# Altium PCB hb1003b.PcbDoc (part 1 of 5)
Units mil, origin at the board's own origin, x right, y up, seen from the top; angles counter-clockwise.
Board outline 2757 x 3548 mil, 2 copper layers (Top Layer, Bottom Layer); 120 components, 120 nets, 466 pads, 329 vias.
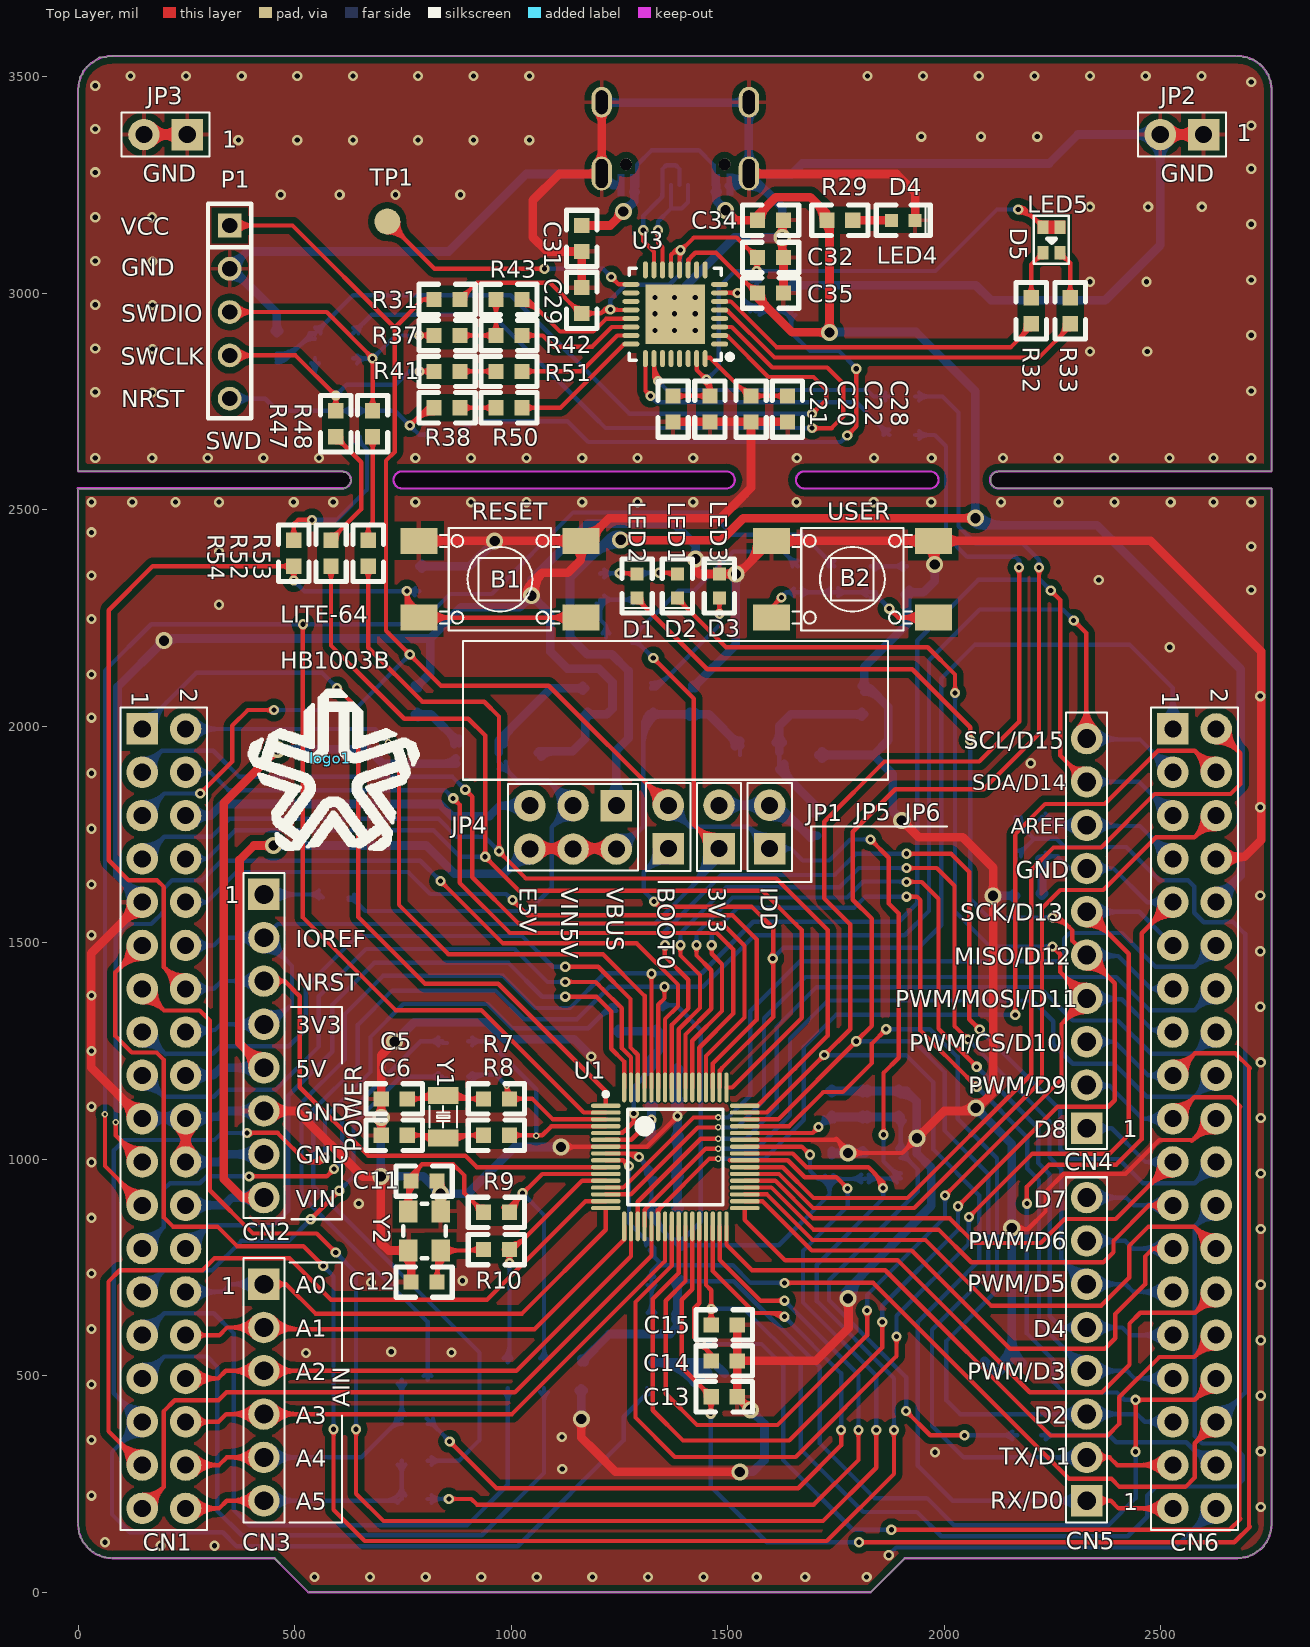
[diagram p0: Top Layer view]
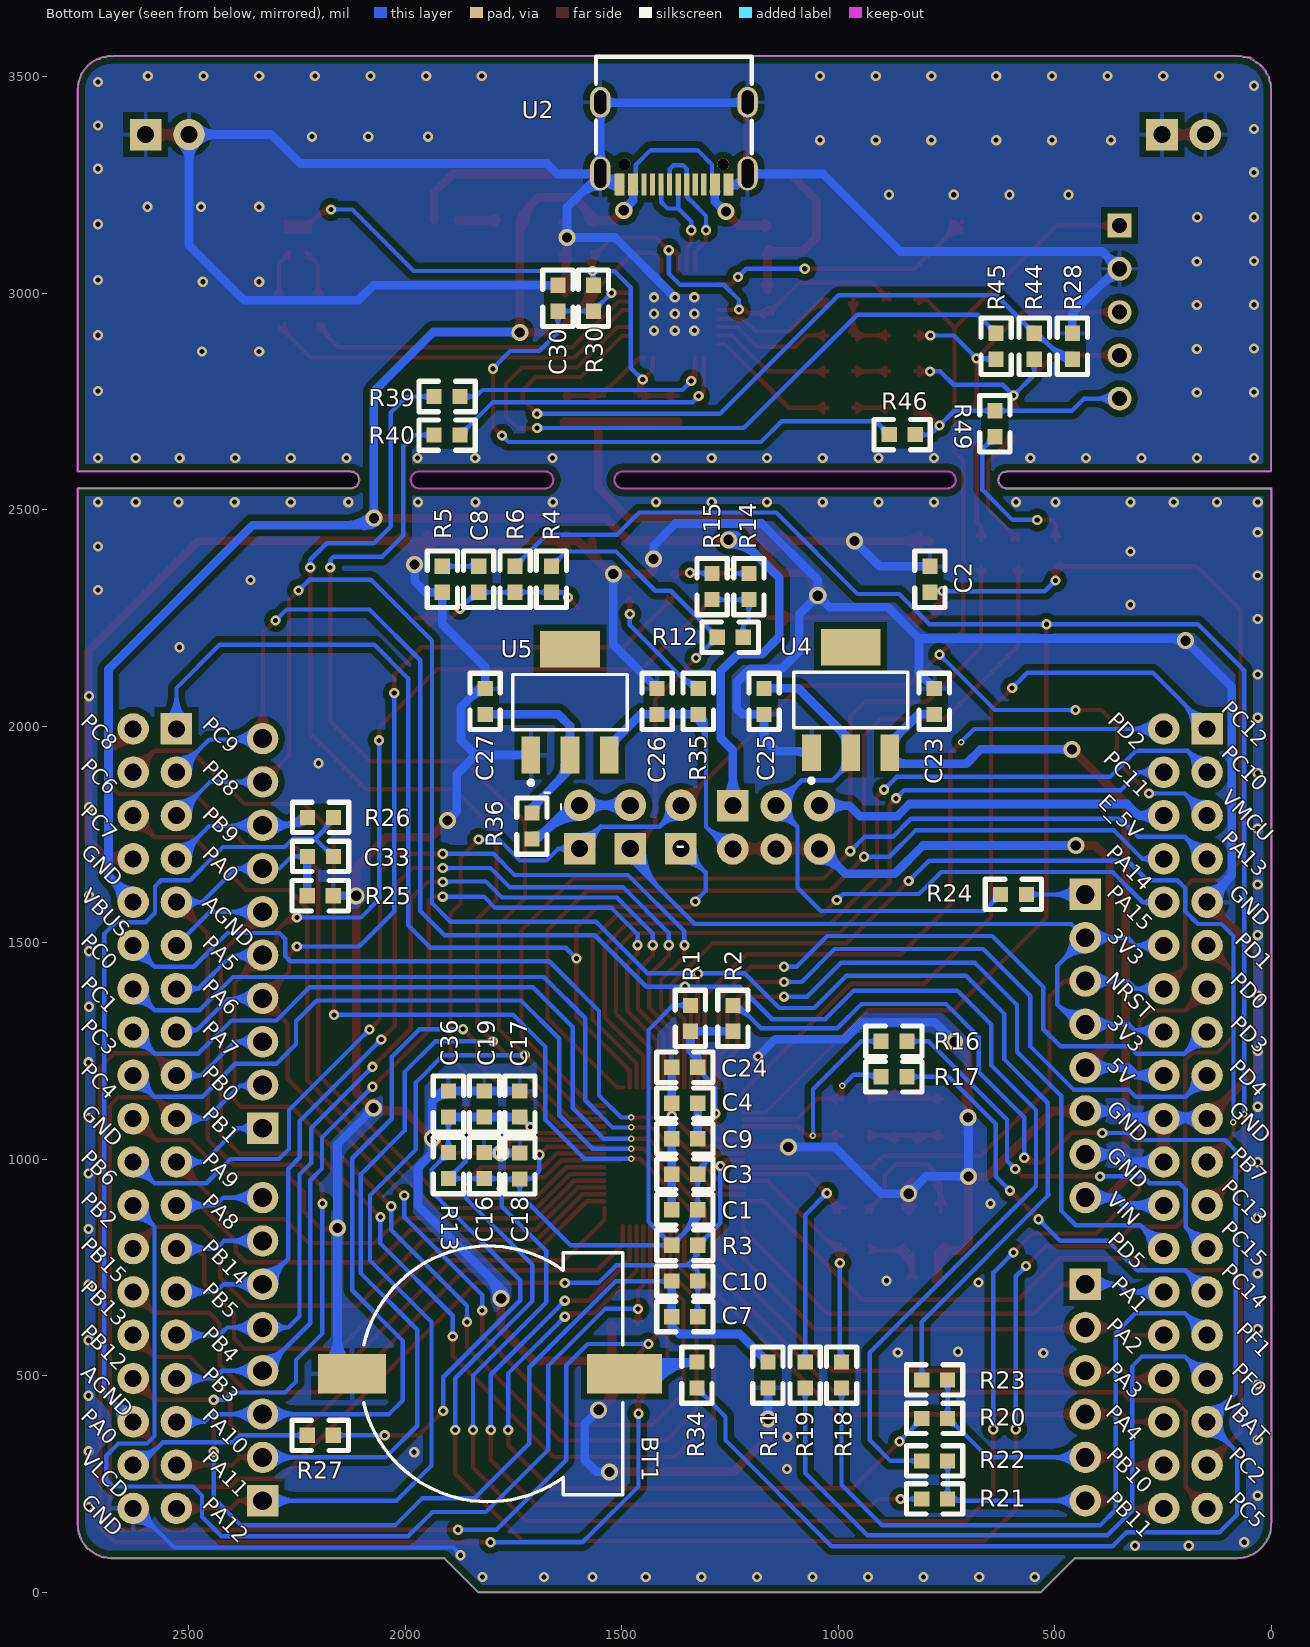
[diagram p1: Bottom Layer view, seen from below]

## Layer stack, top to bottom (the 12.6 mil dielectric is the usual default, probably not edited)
Top Layer: signal copper 1.4
Dielectric: dielectric 12.6, FR-4, Dk 4.8
Bottom Layer: signal copper 1.4

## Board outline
79,3548 2667,3548 2674,3548 2675,3547 2681,3547 2687,3547 2689,3545 2695,3545 2700,3545 2701,3544 2705,3540 2708,3540 2713,3540 2714,3539 2717,3536 2720,3536 2724,3532 2727,3529 2728,3529 2729,3529 2732,3526 2734,3524 2734,3523 2737,3520 2740,3517 2740,3515 2743,3512 2745,3510 2745,3509 2747,3507 2749,3505 2749,3500 2749,3499 2750,3498 2751,3497 2751,3496 2751,3494 2753,3492 2754,3491 2754,3489 2754,3486 2755,3485 2755,3480 2755,3476 2756,3475 2756,3470 2756,2588 2129,2588 2125,2588 2124,2587 2123,2586 2119,2586 2117,2586 2116,2585 2114,2583 2113,2583 2112,2582 2111,2581 2111,2580 2110,2580 2109,2579 2109,2577 2108,2576 2108,2573 2107,2572 2107,2566 2107,2562 2108,2561 2110,2559 2110,2555 2111,2555 2112,2554 2113,2553 2115,2553 2116,2553 2118,2551 2119,2550 2120,2550 2122,2550 2123,2549 2127,2549 2756,2549 2756,156 2756,153 2755,152 2755,149 2755,146 2755,143 2755,140 2754,139 2753,138 2753,137 2753,135 2752,134 2751,133 2751,131 2751,127 2750,126 2748,124 2748,122 2748,121 2747,120 2746,119 2746,118 2746,116 2745,115 2742,112 2742,111 2741,111 2740,110 2739,109 2739,108 2739,105 2738,104 2737,103 2737,102 2737,104 2736,103 2736,102 2735,101 2733,99 2732,99 2729,99 2727,97 2724,94 2723,94 2721,94 2718,91 2716,89 2716,88 2714,88 2712,86 2711,85 2708,85 2706,85 2704,83 2702,81 2698,81 2695,81 2694,80 2688,80 2687,79 2686,78 2678,78 1909,78 1858,27 1831,0 1734,0 532,0 481,51 454,78 426,78 78,78 77,79 73,79 70,79 68,79 65,79 64,80 63,81 62,81 59,81 58,82 57,82 53,82 50,85 49,86 46,86 44,86 43,87 42,88 41,88 40,88 38,90 35,93 33,93 32,93 30,95 28,97 28,99 26,99 25,100 21,104 21,105 19,107 17,109 17,110 14,113 10,117 10,119 10,121 8,123 5,126 5,127 5,130 4,131 2,133 2,134 2,137 1,138 1,142 1,149 0,150 0,154 0,159 -1,160 -1,2548 613,2548 614,2549 615,2550 617,2550 618,2550 619,2551 621,2553 622,2554 624,2556 626,2558 628,2560 628,2562 629,2563 631,2565 631,2566 631,2569 630,2570 628,2572 628,2576 628,2578 626,2580 624,2582 624,2583 623,2583 621,2585 620,2586 617,2586 613,2586 612,2587 611,2588 608,2588 605,2588 0,2588 0,3474 1,3475 1,3481 1,3486 3,3488 4,3489 4,3494 4,3499 7,3502 11,3506 11,3510 11,3513 15,3517 19,3521 19,3522 20,3522 23,3525 30,3532 35,3532 41,3538 48,3545 59,3545 66,3545 67,3546 68,3547 79,3547 80,3547
cut-out: 1678.42,2547.63 1967,2547.63 ccw(c1967,2567.31) 1967,2587 1678.42,2587 ccw(c1678.42,2567.32)
cut-out: 747.97,2549 1496,2549 ccw(c1496,2568.68) 1496,2588.37 747.97,2588.37 ccw(c747.97,2568.68)

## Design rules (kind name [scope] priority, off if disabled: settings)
Clearance [(IsPad and InComponent('U1'))] p1: gap=4
Clearance Clearance_poly [(InPolygon)] p2: gap=15
Clearance Clearance_CN [(IsPad and InComponent('CN1','CN4'))] p3: gap=5
Clearance Clearance_Pad [All] p4: gap=5
ComponentClearance [All] p1: gap=0 collisioncheckmode=3 verticalgap=0 showdistances=FALSE
HoleSize [All] p1: absolutevalues=TRUE maxlimit=130 minlimit=1 maxpercent=80.000 minpercent=20.000
MinimumSolderMaskSliver [All] p1: minsoldermaskwidth=0
PolygonConnect PolygonConnect_Pads [IsPad] p1: connectstyle=Relief reliefconductorwidth=10 reliefentries=4 polygonreliefangle="90 Angle"
PolygonConnect [All] p2: connectstyle=Direct reliefconductorwidth=10 reliefentries=4 polygonreliefangle="90 Angle"
RoutingVias [All] p1: holewidth=12 width=20 viastyle="Through Hole" minholewidth=10 minwidth=18 maxholewidth=300 maxwidth=500
SilkToSilkClearance [All] p1: silktosilkclearance=0
SilkscreenOverComponentPads [IsPad] p1: minsilkscreentomaskgap=0
SolderMaskExpansion [All] p1: expansion=4
TestPointUsage [All] p1: valid=0 allowmultiple=FALSE
Testpoint [All] p1: side=3 testpointundercomponent=TRUE minsize=40 maxsize=100 preferedsize=60 minholesize=0 maxholesize=40 preferedholesize=32 testpointgrid=1 style=297 order=0123456789
Width [All] p1: maxlimit=20 minlimit=8 preferedwidth=10
19 further rules are at their usual default settings.

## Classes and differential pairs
net class PD[0..5]: PD0 PD1 PD2 PD3 PD4 PD5
net class PC[0..15]: PC0 PC1 PC2 PC3 PC4 PC5 PC6 PC7 PC8 PC9 PC10 PC11 PC12 PC13 PC14 PC15
component class hed_link: C20 C21 C22 C28 C29 C30 C31 C32 C34 C35 D4 D5 JP7 JP8 JP9 JP10 JP11 LD1 P1 R28 R29 R30 R31 R32 R33 R37 R38 R39 R40 R41 R42 R43 R44 R45 R46 R47 R48 R49 R50 R51 TP1 U2 U3
component class arduino_extension_interfaces: C19 CN1 CN2 CN3 CN4 CN5 CN6 R16 R17 R18 R19 R20 R21 R22 R23 R24 R25 R26 R27
component class mcu: B1 B2 C1 C2 C3 C4 C5 C6 C7 C8 C9 C10 C11 C12 C13 C14 C15 C16 C17 C18 C24 C33 C36 D1 D2 JP1 logo1 R1 R2 R3 R4 R5 R6 R7 R8 R9 R10 R11 R12 R13 R14 R15 R52 R53 R54 U1 Y1 Y2
component class power: BT1 C23 C25 C26 C27 D3 JP2 JP3 JP4 JP5 JP6 R34 R35 R36 U4 U5
net class PA[0..15]: PA0 PA1 PA2 PA3 PA4 PA5 PA6 PA7 PA8 PA9 PA10 PA11 PA12 PA13 PA14 PA15
net class PB[0..15]: PB0 PB1 PB2 PB3 PB4 PB5 PB6 PB7 PB8 PB9 PB10 PB11 PB12 PB13 PB14 PB15
net class PF[0..1]: PF0 PF1

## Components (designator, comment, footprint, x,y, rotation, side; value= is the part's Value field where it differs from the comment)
B1 "SW-PUSH-CMS_BLACK" SWI_WEALTHMETAL_TD-0341_4P_BLACK 974,2339 r270 top locked
B2 "SW-PUSH-CMS_BLUE" SWI_WEALTHMETAL_TD-0341_4P_BLUE 1788,2339 r270 top locked
BT1 "" CR1220 1493,504 r180 bottom
C1 "4.7u" 0603 1384,883 r180 bottom
C2 "0.1u" 0603 788,2309 r90 bottom
C3 "0.1u" 0603 1384,965 r180 bottom
C4 "0.1u" 0603 1324,1129 r0 bottom
C5 "22p" 0603 700,1139 r0 top
C6 "22p" 0603 700,1055 r0 top
C7 "DNP" 0603 1384,636 r180 bottom
C8 "0.1u" 0603 1830,2369 r270 bottom
C9 "1u" 0603 1324,1047 r0 bottom
C10 "DNP" 0603 1384,718 r180 bottom
C11 "DNP" 0603 769,949 r0 top
C12 "DNP" 0603 829,716 r180 top
C13 "DNP" 0603 1462,451 r0 top
C14 "DNP" 0603 1462,534 r0 top
C15 "DNP" 0603 1462,617 r0 top
C16 "4.7u" 0603 1817,955 r90 bottom
C17 "DNP" 0603 1735,1097 r90 bottom
C18 "0.1u" 0603 1735,954 r90 bottom
C19 "DNP" 0603 1817,1097 r90 bottom
C20 "1u" 0603 1459,2702 r90 top
C21 "10n" 0603 1374,2702 r90 top
C22 "4.7u" 0603 1554,2702 r90 top
C23 "10u" 0603 778,2087 r270 bottom
C24 "0.1u" 0603 1384,1212 r180 bottom
C25 "10u" 0603 1171,2027 r90 bottom
C26 "10u" 0603 1418,2087 r270 bottom
C27 "10u" 0603 1815,2087 r270 bottom
C28 "0.1u" 0603 1638,2702 r90 top
C29 "0.1u" 0603 1163,2953 r90 top
C30 "0.1u" 0603 1647,2958 r90 bottom
C31 "10u" 0603 1163,3096 r90 top
C32 "1u" 0603 1569,3082 r0 top
C33 "DNP" 0603 2225,1699 r180 bottom
C34 "0.1u" 0603 1629,3168 r180 top
C35 "1u" 0603 1569,3000 r0 top
C36 "DNP" 0603 1900,1157 r270 bottom
CN1 "Header 23x2" HEADER_1X19_2.54 148,1993.23 r270 top locked
CN2 "Socket 8x1" HEADER_1X8_2.54 429,1261 r270 top locked
CN3 "Socket 6x1" HEADER_1X6-2.54 429,461 r270 top locked
CN4 "Socket 10x1" HEADER_1X10_2.54 2329,1521 r90 top locked
CN5 "Socket 8x1" HEADER_1X8_2.54 2329,561 r90 top locked
CN6 "Header 23x2" HEADER_1X19_2.54 2528,1993.23 r270 top locked
D1 "LED_B" "0603 - p" 1291,2351 r270 top locked
D2 "LED_P" "0603 - p" 1384,2351 r270 top locked
D3 "LED_R" "0603 - P" 1481,2296 r90 top locked
D4 "LED_R" "0603 - p" 1878,3168 r0 top
D5 "LD_BICOLOR_CMS" LED-SMD_4P_1615 2228,3093 r90 top
JP1 "Shunt Fitted" HEADER_1X2_2.54 1363,1767 r90 top locked
JP2 "Shunt Fitted" CON_SAMTEC_TSW-102-07-G-S 2549,3366 r180 top
JP3 "Shunt Fitted" CON_SAMTEC_TSW-102-07-G-S 202,3366 r180 top locked
JP4 "Shunt Fitted 1-2" HEADER_2X3_2.54 1243,1816 r180 top locked
JP5 "Shunt Fitted" HEADER_1X2_2.54 1480,1767 r90 top locked
JP6 "Shunt Fitted" HEADER_1X2_2.54 1597,1767 r90 top locked
logo1 "logo" 华大电子LOGO 582,1926 r0 top
P1 "SWD" HED_5_4_2.5 350,3156 r270 top locked
R1 "0R" 0603 1341,1295 r90 bottom
R2 "DNP" 0603 1243,1295 r90 bottom
R3 "0R" 0603 1324,801 r0 bottom
R4 "4.7k" 0603 1662,2309 r90 bottom
R5 "100R" 0603 1914,2369 r270 bottom
R6 "0R" 0603 1746,2369 r270 bottom
R7 "0R" 0603 996,1139 r180 top
R8 "0R" 0603 996,1055 r180 top
R9 "DNP" 0603 936,877 r0 top
R10 "DNP" 0603 936,791 r0 top
R11 "0R" 0603 1162,531 r270 bottom
R12 "0R" 0603 1219,2205 r0 bottom
R13 "0R" 0603 1900,1015 r270 bottom
R14 "510R" 0603 1206,2352 r270 bottom
R15 "510R" 0603 1291,2352 r270 bottom
R16 "DNP" 0603 841,1272 r0 bottom
R17 "DNP" 0603 841,1190 r0 bottom
R18 "0R" 0603 992,471 r90 bottom
R19 "0R" 0603 1076,471 r90 bottom
R20 "0R" 0603 747,401 r0 bottom
R21 "0R" 0603 747,215 r0 bottom
R22 "DNP" 0603 807,303 r180 bottom
R23 "DNP" 0603 807,490 r180 bottom
R24 "DNP" 0603 625,1611 r180 bottom
R25 "0R" 0603 2226,1608 r180 bottom
R26 "0R" 0603 2165,1789 r0 bottom
R27 "0R" 0603 2166,362 r0 bottom
R28 "DNP" 0603 459,2847 r90 bottom
R29 "1K" 0603 1729,3168 r0 top
R30 "DNP" 0603 1565,3018 r270 bottom
R31 "DNP" 0603 822,2985 r0 top
R32 "330R" 0603 2201,2929 r90 top
R33 "330R" 0603 2291,2929 r90 top
R34 "0R" 0603 1326,471 r90 bottom
R35 "1K" 0603 1323,2087 r270 bottom
R36 "0R" 0603 1707,1739 r90 bottom
R37 "0R" 0603 882,2902 r180 top
R38 "0R" 0603 882,2735 r180 top
R39 "0R" 0603 1873,2761 r0 bottom
R40 "0R" 0603 1873,2672 r0 bottom
R41 "0R" 0603 882,2819 r180 top
R42 "150R" 0603 1025,2902 r180 top
R43 "150R" 0603 1025,2985 r180 top
R44 "DNP" 0603 547,2907 r270 bottom
R45 "DNP" 0603 635,2907 r270 bottom
R46 "DNP" 0603 882,2673 r180 bottom
R47 "0R" 0603 595,2668 r90 top
R48 "0R" 0603 680,2668 r90 top
R49 "0R" 0603 638,2668 r90 bottom
R50 "150R" 0603 1025,2735 r180 top
R51 "150R" 0603 1025,2819 r180 top
R52 "10R" 0603 584,2429 r270 top
R53 "10R" 0603 670,2429 r270 top
R54 "10R" 0603 498,2429 r270 top
TP1 "TEST_POINT" TEST_POINT 719,3203 r90 top
U1 "MCU" LQFP_64N_7X7 1379,1005 r0 top locked
U2 "TYPE-C-16P" HED-KH-TYPE-C-16P 1209,3276 r0 bottom locked
U3 "MCU" HED-QFN-32_5x5x05P 1379,2951 r90 top
U4 "AMS1117-5V" SOT223 971,2060 r180 bottom locked
U5 "AMS1117-3V3" SOT223 1619,2055 r180 bottom locked
Y1 "YST310S" CRY_3215SA_2P 843,1098 r270 top
Y2 "DNP" "3.2*2.5*0.7 OSC" 800,834 r270 top

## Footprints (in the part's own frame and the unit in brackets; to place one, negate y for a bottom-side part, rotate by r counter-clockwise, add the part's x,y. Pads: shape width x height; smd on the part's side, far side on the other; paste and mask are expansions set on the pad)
"3.2*2.5*0.7 OSC" [mm]
  rect 1.3x1.1 smd: 1(-1.15,-0.95) 2(1.15,-0.95) 3(1.15,0.95) 4(-1.15,0.95)
  round 0.25 on Top Overlay: 12(-2.075,-1.375)
  silkscreen extent -1.6,-1.25 1.6,1.25, body extent -1.6,-1.28 1.6,1.25, height 0.7
0603 [mil]
  rect 35x35 smd: 1(0,0) 2(60,0)
  silkscreen extent -35,-35 95,35
"0603 - p" [mil]
  rect 30x30 smd: 1(0,0) 2(55,0)
  silkscreen extent -35,-35 90,35, body extent 1,-15 60,15, height 10
"0603 - P" [mil]
  rect 30x30 smd: 1(0,0) 2(55,0)
  silkscreen extent -35,-35 90,35, body extent 1,-15 60,15, height 10
CON_SAMTEC_TSW-102-07-G-S [mm]
  rect 1.85x1.85 / inner round 1.85 / far side rect 1.85x1.85 hole 1: 1(-1.27,0)
  round 1.85 hole 1: 2(1.27,0)
  silkscreen extent -2.58,-1.3 2.58,1.3, body extent -2.67,-1.3 2.58,1.3, height 8.38
CR1220 [mm]
  rect 4.4x2.3 smd: 1(0,0)
  rect 4x2.3 smd: 2(-16,0)
  silkscreen extent -15.31,-7.5 -0.1,7.5
CRY_3215SA_2P [mm]
  rect 1x1.8 smd: 1(-1.25,0) 2(1.25,0)
  silkscreen extent -0.63,-0.8 0.63,0.8, body extent -1.65,-0.8 1.65,0.8, height 0.9
HEADER_1X2_2.54 [mm]
  rect 1.85x1.85 / inner round 1.85 / far side rect 1.85x1.85 hole 1: 1(-1.27,0)
  round 1.85 hole 1: 2(1.27,0)
  silkscreen extent -2.58,-1.3 2.58,1.3, body extent -2.67,-1.3 2.58,1.3, height 8.38
HEADER_1X6-2.54 [mm]
  rect 1.85x1.85 / inner round 1.85 / far side rect 1.85x1.85 hole 1.1: 1(-6.35,0)
  round 1.85 hole 1.1: 2(-3.81,0) 3(-1.27,0) 4(1.27,0) 5(3.81,0) 6(6.35,0)
  silkscreen extent -7.88,-1.2 7.62,1.2, body extent -7.88,-1.21 7.88,1.21, height 8.51
HEADER_1X8_2.54 [mm]
  rect 1.85x1.85 / inner round 1.85 / far side rect 1.85x1.85 hole 1.1: 1(-8.89,0)
  round 1.85 hole 1.1: 2(-6.35,0) 3(-3.81,0) 4(-1.27,0) 5(1.27,0) 6(3.81,0) 7(6.35,0) 8(8.89,0)
  silkscreen extent -10.16,-1.2 10.08,1.2, body extent -10.42,-1.21 10.42,1.21, height 8.51
HEADER_1X10_2.54 [mm]
  rect 1.85x1.85 / inner round 1.85 / far side rect 1.85x1.85 hole 1.1: 1(-11.43,0)
  round 1.85 hole 1.1: 2(-8.89,0) 3(-6.35,0) 4(-3.81,0) 5(-1.27,0) 6(1.27,0) 7(3.81,0) 8(6.35,0) 9(8.89,0) 10(11.43,0)
  silkscreen extent -12.65,-1.2 12.96,1.2, body extent -12.96,-1.21 12.96,1.21, height 8.51
HEADER_1X19_2.54 [mm]
  rect 1.85x1.85 / inner round 1.85 / far side rect 1.85x1.85 hole 1: 1(0,0)
  round 1.85 hole 1: 2(0,2.54) 3(2.54,0) 4(2.54,2.54) 5(5.08,0) 6(5.08,2.54) 7(7.62,0) 8(7.62,2.54) 9(10.16,0) 10(10.16,2.54) 11(12.7,0) 12(12.7,2.54) 13(15.24,0) 14(15.24,2.54) 15(17.78,0) 16(17.78,2.54) 17(20.32,0) 18(20.32,2.54) 19(22.86,0) 20(22.86,2.54) 21(25.4,0) 22(25.4,2.54) 23(27.94,0) 24(27.94,2.54) 25(30.48,0) 26(30.48,2.54) 27(33.02,0) 28(33.02,2.54) 29(35.56,0) 30(35.56,2.54) 31(38.1,0) 32(38.1,2.54) 33(40.64,0) 34(40.64,2.54) 35(43.18,0) 36(43.18,2.54) 37(45.72,0) 38(45.72,2.54)
  silkscreen extent -1.27,-1.27 46.99,3.81, body extent -1.27,-1.27 46.99,3.81, height 8.38
HEADER_2X3_2.54 [mm]
  rect 1.85x1.85 / inner round 1.85 / far side rect 1.85x1.85 hole 1: 1(0,0)
  round 1.85 hole 1: 2(0,2.54) 3(2.54,0) 4(2.54,2.54) 5(5.08,0) 6(5.08,2.54)
  silkscreen extent -1.27,-1.27 6.35,3.81, body extent -1.27,-1.33 8.89,3.87, height 8.38
HED-KH-TYPE-C-16P [mm]
  oval 1.2x2 hole 0.7 slot 1.7 at 90 deg: 1(0,0) 2(8.64,0)
  oval 1.2x1.8 hole 0.7 slot 1.4 at 90 deg: 3(0,-4.18) 4(8.64,-4.18)
  rect 0.3x1.3 smd: A1(0.97,0.65) A4(1.77,0.65) A5(3.07,0.65) A6(4.07,0.65) A7(4.57,0.65) A8(5.57,0.65) A9(6.87,0.65) A12(7.67,0.65) B1(7.37,0.65) B4(6.57,0.65) B5(6.07,0.65) B6(5.07,0.65) B7(3.57,0.65) B8(2.57,0.65) B9(2.07,0.65) B12(1.27,0.65)
  round 0.7 hole 0.7 unplated: ""(1.43,-0.53) ""(7.21,-0.53)
  silkscreen extent -0.25,-6.84 8.89,-1.19
HED-QFN-32_5x5x05P [mm]
  oval 0.28x1 smd: 1(-1.75,-2.6) 2(-1.25,-2.6) 3(-0.75,-2.6) 4(-0.25,-2.6) 5(0.25,-2.6) 6(0.75,-2.6) 7(1.25,-2.6) 8(1.75,-2.6) 17(1.75,2.6) 18(1.25,2.6) 19(0.75,2.6) 20(0.25,2.6) 21(-0.25,2.6) 22(-0.75,2.6) 23(-1.25,2.6) 24(-1.75,2.6)
  oval 1x0.28 smd: 9(2.6,-1.75) 10(2.6,-1.25) 11(2.6,-0.75) 12(2.6,-0.25) 13(2.6,0.25) 14(2.6,0.75) 15(2.6,1.25) 16(2.6,1.75) 25(-2.6,1.75) 26(-2.6,1.25) 27(-2.6,0.75) 28(-2.6,0.25) 29(-2.6,-0.25) 30(-2.6,-0.75) 31(-2.6,-1.25) 32(-2.6,-1.75)
  rect 3.5x3.5 smd: 33(0,0)
  silkscreen extent -2.7,-3.35 2.7,2.7
HED_5_4_2.5 [mil]
  rect 55x55 hole 35: 1(0,0)
  round 55 hole 35: 2(100,0) 3(200,0) 4(300,0) 5(400,0)
  silkscreen extent -50,-50 445,50
LED-SMD_4P_1615 [mm]
  rect 0.8x0.65 smd: 1(0,0) 2(1.5,0) 3(0,-1) 4(1.5,-1)
  silkscreen extent -0.64,-1.52 2.16,0.54
LQFP_64N_7X7 [mm] "TSQFP, 64-Leads, Body 9.2x9.2mm (max), Pitch 0.40mm, IPC Medium Density"
  oval 1.75x0.25 smd: 1(-4.075,3) 2(-4.075,2.6) 3(-4.075,2.2) 4(-4.075,1.8) 5(-4.075,1.4) 6(-4.075,1) 7(-4.075,0.6) 8(-4.075,0.2) 9(-4.075,-0.2) 10(-4.075,-0.6) 11(-4.075,-1) 12(-4.075,-1.4) 13(-4.075,-1.8) 14(-4.075,-2.2) 15(-4.075,-2.6) 16(-4.075,-3) 33(4.075,-3) 34(4.075,-2.6) 35(4.075,-2.2) 36(4.075,-1.8) 37(4.075,-1.4) 38(4.075,-1) 39(4.075,-0.6) 40(4.075,-0.2) 41(4.075,0.2) 42(4.075,0.6) 43(4.075,1) 44(4.075,1.4) 45(4.075,1.8) 46(4.075,2.2) 47(4.075,2.6) 48(4.075,3)
  oval 0.25x1.75 smd: 17(-3,-4.075) 18(-2.6,-4.075) 19(-2.2,-4.075) 20(-1.8,-4.075) 21(-1.4,-4.075) 22(-1,-4.075) 23(-0.6,-4.075) 24(-0.2,-4.075) 25(0.2,-4.075) 26(0.6,-4.075) 27(1,-4.075) 28(1.4,-4.075) 29(1.8,-4.075) 30(2.2,-4.075) 31(2.6,-4.075) 32(3,-4.075) 49(3,4.075) 50(2.6,4.075) 51(2.2,4.075) 52(1.8,4.075) 53(1.4,4.075) 54(1,4.075) 55(0.6,4.075) 56(0.2,4.075) 57(-0.2,4.075) 58(-0.6,4.075) 59(-1,4.075) 60(-1.4,4.075) 61(-1.8,4.075) 62(-2.2,4.075) 63(-2.6,4.075) 64(-3,4.075)
  silkscreen extent -4.2,-2.8 2.8,3.8, body extent -3.5,-3.5 3.5,3.5, height 1.4
SOT223 [mm] "SOT-223/SC-73; 4 Leads; Body 6.7 x 7.3 mm, inc. leads (LxW max)"
  rect 1.1x2.15 smd: 1(-2.3,-3.1) 2(0,-3.1) 3(2.3,-3.1)
  rect 3.5x2.15 smd: 4(0,3.1)
  silkscreen extent -3.35,-4.85 3.35,1.63
SWI_WEALTHMETAL_TD-0341_4P_BLACK [mm]
  rect 1.52x2.16 smd: 1(-2.25,-4.75) 2(-2.25,4.75) 3(2.25,-4.75) 4(2.25,4.75)
  silkscreen extent -3,-3.5 3,3.5, body extent -3,-5.15 3,5.15, height 7.55
SWI_WEALTHMETAL_TD-0341_4P_BLUE [mm]
  rect 1.52x2.16 smd: 1(-2.25,-4.75) 2(-2.25,4.75) 3(2.25,-4.75) 4(2.25,4.75)
  silkscreen extent -3,-3.5 3,3.5, body extent -3,-5.15 3,5.15, height 7.55
TEST_POINT [mil]
  round 60 smd: 1(-38,5)
华大电子LOGO [mil]
  silkscreen extent -187,-211 203,157

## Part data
B1: library part MCD-00001, "Non-Open Push-Button 0.1A 24V"
B2: library part MCD-00002, "Non-Open Push-Button 0.1A 24V"
BT1: library part Battery, "Multicell Battery"
C1 C11 C12 C13 C14 C15 C16 C17 C19 C36: library part MCD-00009, "Capacitor, MLCC, 4.7uF, 16V, X5R, 10%, 0603, T=0.8mm"
C2: library part Capacitor, "Capacitor, MLCC, 100nF, 16V, X7R, 10%, 0603, T=0,8mm"
C3 C4 C7 C9 C10 C18 C20 C21 C28 C29 C30 C32 C33 C35: library part MCD-00211, "Capacitor, MLCC, 100nF, 16V, X7R, 10%, 0603, T=0,8mm"
C5 C6: library part Capacitor, "Capacitor,5.6pF,0.1pF,16V,NPO,0603"
C8: library part MCD-00211, "贴片电容"
C22 C34: library part "0603 100nF 10% 50V", "贴片电容"
C23 C24 C25 C26 C27: library part MCD-00014, "Capacitor, MLCC, 10uF, 25V, X5R, 10%, 0805, T=0,85mm"
C31: library part "0603 4.7uF 10% 16V", "贴片电容"
CN1 CN6: "Header, 19x2, 2,54mm, VR, TH, Height 5.84mm/10.16mm"
CN2 CN5: "Socket, 8x1, 2.54mm, VR, TH, Height 8.51mm/10mm"
CN3: "Socket, 6x1, 2.54mm, VR, TH, Height 8.51mm/10mm"
CN4: "Socket, 10x1, 2.54mm, VR, TH, Height 8.51mm/10mm"
D1 D2 D3: library part LED1, "Typical RED GaAs LED"
D4: library part LED3, "Typical BLUE SiC LED"
D5: "LED Bicolor"
JP1 JP5 JP6: library part "Jumper_Header 2x1 Fitted", "Header, 2x1, 2,54mm, VR, TH, Height 5.84mm/2.54mm - Shunt Fitted by default"
JP2 JP3: library part MCD-00683, "Header, 2x1, 2,54mm, VR, TH, Height 5.84mm/2.54mm - Shunt Fitted by default"
JP4: library part "Jumper_Header 4x2 Fitted 1-2", "Header, 4x2, 2,54mm, VR, TH, Height 5.84mm/2.54mm - Shunt Fitted 1-2"
R1 R2 R3 R4 R5 R6 R7 R8 R9 R10 R11 R12 R13 R14 R15 R16 R17 R18 R19 R20 R21 R22 R23 R24 R25 R26 R27 R29 R30 R31 R32 R33 R34 R35 R36 R37 R38 R39 R40 R41 R42 R43 R50 R51 R52 R53 R54: library part Res2, "贴片电阻"
R28 R44 R45 R46 R47 R48 R49: library part Res, "贴片电阻"
U1: library part LQFP64
U2: library part KH-TYPE-C-16P, "TYPE-C USB接口"
U3: library part CIU98-H
U4 U5: "IC REG LDO 5V 0.8A SOT223"
Y1: library part XTAL_32K_NX3215SA, "32.768k无源晶振"
Y2: library part XTAL_4

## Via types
v1: diameter 23.62, hole 11.81, Top Layer to Bottom Layer, tented both sides, 290 vias
v2: diameter 39.37, hole 23.62, Top Layer to Bottom Layer, tented both sides, 29 vias
v3: diameter 15, hole 8, Top Layer to Bottom Layer, tented both sides, 10 vias

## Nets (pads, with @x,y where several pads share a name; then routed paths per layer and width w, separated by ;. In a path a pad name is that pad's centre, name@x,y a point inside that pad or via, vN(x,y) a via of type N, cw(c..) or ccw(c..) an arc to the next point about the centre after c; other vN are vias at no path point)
AGND: C7.1 C10.1 C33.1 CN4.7 CN6.9 CN6.32 R11.1 R25.1 | length 5354.7
  Top Layer w10: v1@2186.18,901.82 ccw(c2174.56,913.44) 2191,913.44 ccw(c2207.44,913.44) v1@2195.82,901.82 ; v1(2191,897) 2191,936 2242,987 2397,987 2456,1046 2456,1130 ; v1@2437.18,328.82 ccw(c2425.56,340.44) 2442,340.44 ccw(c2458.44,340.44) v1@2446.82,328.82 ; v1@2437.18,439.18 cw(c2425.56,427.56) 2442,427.56 cw(c2458.44,427.56) 2446.82,439.18 cw(c2458.44,427.56) 2458.44,444 cw(c2458.44,460.44) v1@2446.82,448.82 ; v1(2442,324) v1(2442,444) 2578.77,444 ; 2456,1121 2456,1130 ; CN6.9@2496.58,1593.23 cw(c2420.73,1593.23) 2474.37,1539.6 cw(c2528,1485.96) CN6.9@2528,1561.81 ; CN6.9@2506.58,1593.23 cw(c2454.88,1593.23) 2491.44,1556.67 cw(c2528,1520.11) CN6.9@2528,1571.81 ; CN6.9@2525.61,1595.61 CN6.9@2528,1598 ; CN6.9@2528,1593.23 2456,1521.23 2456,1130 ; CN6.32@2596.64,491.27 cw(c2535.34,487.43) 2578.77,444 ; CN6.32@2606.62,491.89 cw(c2564.84,489.28) 2594.44,459.67 cw(c2624.05,430.06) CN6.32@2626.66,471.85 ; CN6.32@2625.61,495.61 CN6.32@2628,498 ; CN6.32@2626.04,461.87 ccw(c2622.2,400.57) 2578.77,444 ; CN6.32@2628,493.23 2578.77,444
  Bottom Layer w10: C10.1@1384,718 1514,718 1713,519 1713,343 1839,217 1960,217 2023,154 2379,154 2442,217 v1(2442,324) ; C10.1@1392.84,709.16 cw(c1414.18,687.82) 1414.18,718 cw(c1414.18,748.18) C10.1@1392.84,726.84 ; v1@2186.18,892.18 cw(c2174.56,880.56) 2191,880.56 cw(c2207.44,880.56) v1@2195.82,892.18 ; v1(2191,897) 2191,597 2252,536 2252,486 2277,461 2399,461 2416,444 v1(2442,444) ; C33.1@2222,1691 2226,1691 C33.1@2226,1693 ; C33.1@2225,1699 2262,1699 2290,1671 CN4.7@2329,1671 ; C33.1@2233.84,1690.16 cw(c2255.18,1668.82) 2255.18,1699 cw(c2255.18,1729.18) C33.1@2233.84,1707.84 ; CN4.7@2327,1669 CN4.7@2329,1671 ; CN4.7@2346.27,1658.34 cw(c2371.26,1640.01) 2371.26,1671 cw(c2371.26,1701.99) CN4.7@2346.27,1683.66 ; CN4.7@2354.34,1652.42 cw(c2391,1625.54) 2391,1671 ; CN4.7@2354.34,1689.58 ccw(c2391,1716.46) 2391,1671 ; v1@2437.18,319.18 cw(c2425.56,307.56) 2442,307.56 cw(c2458.44,307.56) v1@2446.82,319.18 ; v1@2437.18,439.18 ccw(c2425.56,427.56) 2425.56,444 ccw(c2425.56,460.44) v1@2437.18,448.82 ; CN6.9@2501.99,1575.61 ccw(c2468.77,1553.11) 2468.77,1593.23 ; CN6.9@2501.99,1610.85 cw(c2468.77,1633.34) 2468.77,1593.23 ; CN6.9@2510.27,1581.22 ccw(c2487.63,1565.88) 2487.63,1593.23 ccw(c2487.63,1620.57) CN6.9@2510.27,1605.24 ; CN6.9@2528,1593.23 2468.77,1593.23 ; CN4.7@2329,1671 2391,1671 ; 2391,1671 2468.77,1593.23
  Bottom Layer w20: R11.1@1162,531 1227,596 1367,596 1384,613 C7.1@1384,636 ; R11.1@1162,538.5 ccw(c1162,556.61) 1174.8,543.8 ccw(c1187.61,531) R11.1@1169.5,531 ; 1378.5,607.5 ccw(c1366.8,619.2) C7.1@1378.63,630.76 ; C7.1@1378.7,630.7 cw(c1365.89,617.89) 1384,617.89 cw(c1402.11,617.89) C7.1@1389.3,630.7 ; C7.1@1378.7,641.3 ccw(c1365.89,654.11) 1384,654.11 ccw(c1402.11,654.11) C7.1@1389.3,641.3 ; C10.1@1378.7,712.7 cw(c1365.89,699.89) 1384,699.89 cw(c1402.11,699.89) C10.1@1389.3,712.7 ; C7.1@1380.21,636 C7.1@1384,636 ; C10.1@1384,718 C7.1@1384,636 ; C33.1@2219.7,1693.7 cw(c2204.48,1678.47) 2226,1678.47 ; R25.1@2220.7,1613.3 ccw(c2207.89,1626.11) 2226,1626.11 ccw(c2244.11,1626.11) R25.1@2231.3,1613.3 ; R25.1@2226,1608 C33.1@2226,1691
CMS_STATE: TP1.1 U3.17 | length 877.3
  Top Layer w10: TP1.1@714,3140 cw(c714,3079.64) 756.68,3122.32 cw(c799.36,3165) TP1.1@739,3165 ; TP1.1@714,3150 cw(c714,3113.79) 739.61,3139.39 cw(c765.21,3165) TP1.1@729,3165 ; TP1.1@714,3165 823,3056 v1(1077,3056) ; v1@1072.18,3051.18 ccw(c1060.56,3039.56) 1060.56,3056 ccw(c1060.56,3072.44) v1@1072.18,3060.82 ; v1@1231,3030.19 cw(c1231,3013.75) 1242.63,3025.37 cw(c1254.25,3037) v1@1237.81,3037 ; v1@1232,3036 1248.1,3019.9 U3.17@1278.61,3019.9
  Bottom Layer w10: v1@1078,3056 1212,3056 v1(1231,3037) ; v1@1081.82,3051.18 cw(c1093.44,3039.56) 1093.44,3056 cw(c1093.44,3072.44) v1@1081.82,3060.82 ; v1@1224.19,3037 ccw(c1207.75,3037) 1219.37,3048.63 ccw(c1231,3060.25) v1@1231,3043.81
EXTERN_5V: CN1.6 JP4.5 | length 1130.2
  Bottom Layer w10: JP4.5@1043,1816.24 1041.24,1818 JP4.5@1069,1818
  Bottom Layer w20: CN1.6@248,1793.23 289,1793.23 ; CN1.6@267.88,1775.83 cw(c306.23,1742.27) 306.23,1793.23 ; CN1.6@267.88,1810.63 ccw(c306.22,1844.18) 306.22,1793.23 ; 978.63,1816.24 cw(c978.63,1751.63) JP4.5@1024.32,1797.32 ; 979.81,1816.24 ccw(c979.81,1879.19) JP4.5@1024.32,1834.68 ; JP4.5@1043,1816.24 974.24,1816.24 950,1792 863,1792 835,1820 333,1820 311,1798 306.23,1793.23 ; 289,1793.23 cw(c289,1811.83) 272.06,1804.14 ccw(c289,1811.83) 289,1793.23 ; 289,1793.23 ccw(c289,1774.62) 272.06,1782.31 cw(c289,1774.62) 289,1793.23 ; 289,1793.23 306.23,1793.23
EXTERN_VLCD: C17.1 C19.1 C36.2 R13.1 R27.1 U1.44 | length 2030.8
  Top Layer w10: U1.44@1539.43,1060.12 1696.12,1060.12 v1(1710,1074) ; v1@1703.19,1074 cw(c1686.75,1074) 1698.37,1062.37 cw(c1710,1050.75) v1@1710,1067.19 ; v1@1912,411.19 cw(c1912,394.75) 1923.63,406.37 cw(c1935.25,418) v1@1918.81,418 ; v1@1913,419 1913,417 1968,362 v1(2047,362) ; v1@2042.18,357.18 ccw(c2030.56,345.56) 2030.56,362 ccw(c2030.56,378.44) v1@2042.18,366.82
  Bottom Layer w10: v1@1708.54,1073.54 cw(c1735,1047.08) C17.1@1735,1084.5 ; v1@1710,1075 1732,1097 C17.1@1735,1097 ; v1@1710,1080.81 ccw(c1710,1094.84) C17.1@1719.92,1084.92 ; v1@1715.78,1080.78 ccw(c1699.56,1097) C17.1@1722.5,1097 ; v1@1716.81,1074 cw(c1735.67,1074) C17.1@1722.33,1087.33 ; C17.1@1746,1087 C17.1@1746,1101 ; R13.1@1891.16,1023.84 ccw(c1869.83,1045.17) 1900,1045.17 ; C36.2@1891.16,1088.16 cw(c1869.83,1066.83) 1900,1066.83 ; R13.1@1900,1002.5 cw(c1900,972.32) 1921.34,993.66 cw(c1942.68,1015) R13.1@1912.5,1015 ; 1900,1045.18 ccw(c1930.18,1045.18) R13.1@1908.84,1023.84 ; 1900,1066.82 cw(c1930.18,1066.82) C36.2@1908.84,1088.16 ; C36.2@1900,1097 R13.1@1900,1015 1939,976 1939,925 1734,720 1734,674 1912,496 v1(1912,418) ; v1@1907.18,422.82 ccw(c1895.56,434.44) 1912,434.44 ccw(c1928.44,434.44) v1@1916.82,422.82 ; v1(2047,362) R27.1@2166,362 R27.1@2169,362 ; v1@2051.82,357.18 cw(c2063.45,345.55) 2063.45,362 cw(c2063.44,378.44) v1@2051.82,366.82 ; R27.1@2157.16,353.16 ccw(c2135.82,331.82) 2135.82,362 ccw(c2135.82,392.18) R27.1@2157.16,370.84
  Bottom Layer w20: C17.1@1737,1097 C19.1@1817,1097 ; C17.1@1740.3,1091.7 cw(c1753.11,1078.89) 1753.11,1097 cw(c1753.11,1115.11) C17.1@1740.3,1102.3 ; C19.1@1811.7,1091.7 ccw(c1798.89,1078.89) 1798.89,1097 ccw(c1798.89,1115.11) C19.1@1811.7,1102.3 ; C19.1@1820,1097 C19.1@1817,1097 ; C19.1@1822.3,1091.7 cw(c1835.11,1078.89) 1835.11,1097 cw(c1835.11,1115.11) C19.1@1822.3,1102.3 ; C36.2@1894.7,1091.7 ccw(c1881.89,1078.89) 1881.89,1097 ccw(c1881.89,1115.11) C36.2@1894.7,1102.3 ; C36.2@1900,1097 C19.1@1817,1097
